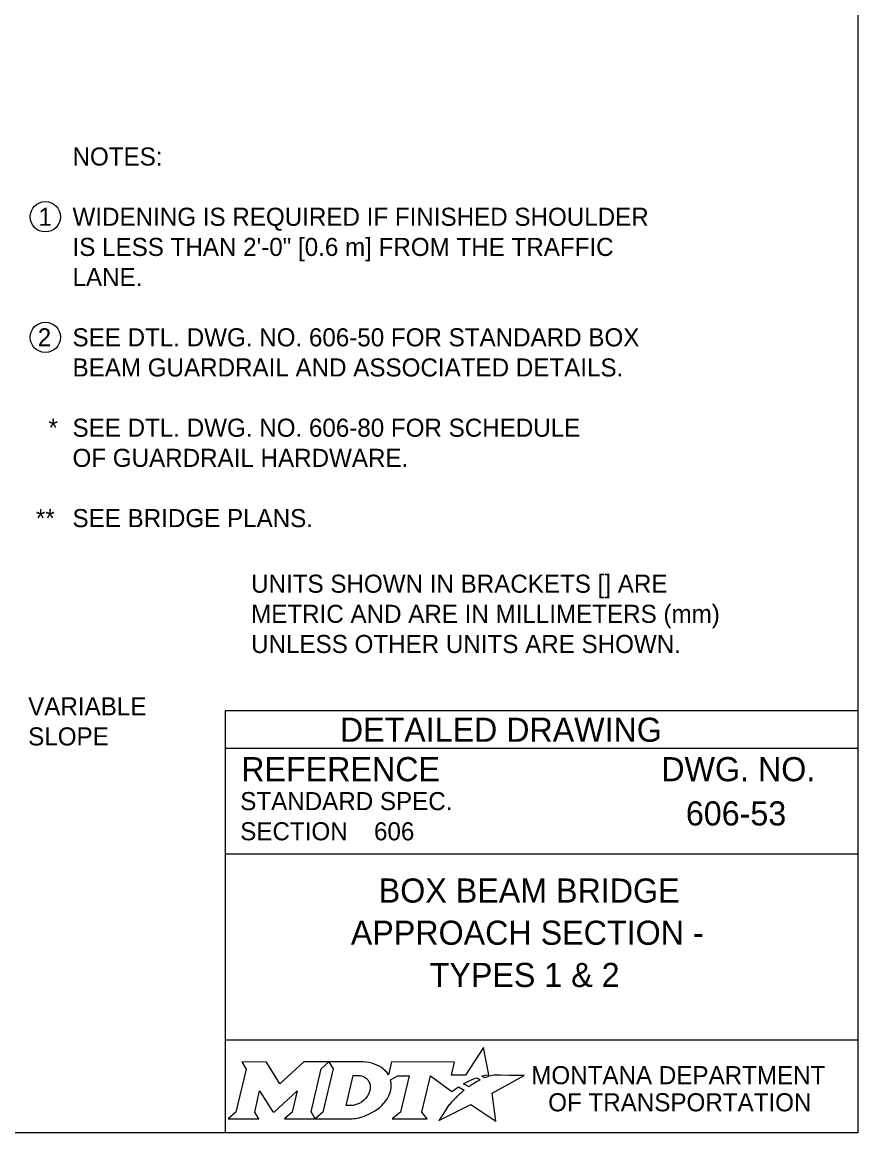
# Model space of a CAD drawing. Extents: x 49991.4 to 50021, y 49987.6 to 50011.4.
# Drawn here: x 50013.977 to 50016.75, y 49987.799 to 49991.484 of the extents above; entities that cross this region are included whole.
import ezdxf

# ---------------------------------------------------------------- set-up
doc = ezdxf.new("R2010")
doc.units = 0
for name, color, linetype in [('Default', 7, 'Continuous'), ('Level 1', 7, 'Continuous'), ('Level 2', 7, 'Continuous'), ('Level 5', 7, 'Continuous')]:
    doc.layers.add(name, color=color, linetype=linetype)

msp = doc.modelspace()

# ---------------------------------------------------------------- linework, layer by layer
at = {"layer": 'Default'}
for points in [[(50015.5126, 49987.9811), (50015.5023, 49987.9867), (50015.5139, 49987.9895), (50015.5255, 49987.9915), (50015.5081, 49988.0816), (50015.4486, 49987.9903), (50015.4013, 49987.9896), (50015.4116, 49988.0337), (50015.2024, 49988.0338), (50015.1923, 49987.9913), (50015.1865, 49987.9996)], [(50014.7056, 49988.0338), (50014.7197, 49988.0104), (50014.6862, 49987.8671), (50014.6605, 49987.8446), (50014.7621, 49987.8446), (50014.7486, 49987.8674), (50014.7648, 49987.9375), (50014.8085, 49987.8685), (50014.8138, 49987.8685), (50014.8889, 49987.938), (50014.8725, 49987.8669), (50014.8478, 49987.8449), (50014.9494, 49987.8449), (50014.9356, 49987.8682), (50014.9688, 49988.0106)], [(50014.9688, 49988.0106), (50014.9941, 49988.0338), (50014.9117, 49988.0338), (50014.8321, 49987.9608), (50014.7876, 49988.0335), (50014.7056, 49988.0338)], [(50015.1077, 49988.0338), (50014.9941, 49988.0338), (50015.0088, 49988.0109), (50014.9749, 49987.8671), (50014.9494, 49987.8449), (50015.06, 49987.8449)], [(50015.1317, 49987.9471), (50015.1305, 49987.939), (50015.1273, 49987.9297), (50015.1231, 49987.9215), (50015.1175, 49987.914), (50015.111, 49987.9071), (50015.1031, 49987.9008), (50015.0948, 49987.8961), (50015.0857, 49987.8922), (50015.0766, 49987.8899), (50015.0674, 49987.889), (50015.0515, 49987.889), (50015.0751, 49987.989), (50015.0911, 49987.989), (50015.0987, 49987.9884), (50015.1063, 49987.9865), (50015.1129, 49987.9835), (50015.119, 49987.9793), (50015.1238, 49987.9743), (50015.1275, 49987.9683), (50015.1302, 49987.9621), (50015.1318, 49987.9547), (50015.1318, 49987.9517), (50015.1317, 49987.9471)], [(50015.1991, 49987.9747), (50015.2237, 49987.9878), (50015.2606, 49987.9878), (50015.232, 49987.8673), (50015.2045, 49987.8446), (50015.3207, 49987.8446), (50015.3037, 49987.8675), (50015.3319, 49987.9877), (50015.4032, 49987.936), (50015.4243, 49987.9511), (50015.444, 49987.9402)], [(50015.3882, 49987.8843), (50015.3729, 49987.8599), (50015.3682, 49987.8524), (50015.3624, 49987.8438), (50015.3601, 49987.8395), (50015.4654, 49987.8926), (50015.5493, 49987.8375), (50015.5362, 49987.9302), (50015.6431, 49987.9886), (50015.5938, 49987.9894), (50015.5637, 49987.9898), (50015.5429, 49987.9901), (50015.5361, 49987.9886), (50015.5312, 49987.9874), (50015.5228, 49987.9851), (50015.5126, 49987.9811)], [(50015.4622, 49987.9535), (50015.4598, 49987.9518), (50015.4415, 49987.9614), (50015.4518, 49987.9671), (50015.4559, 49987.9693), (50015.4645, 49987.9733), (50015.4702, 49987.9759), (50015.4781, 49987.9789), (50015.4854, 49987.9816), (50015.4972, 49987.9742), (50015.4932, 49987.9721), (50015.4886, 49987.9696), (50015.4844, 49987.9674), (50015.4794, 49987.9645), (50015.4775, 49987.9634), (50015.4748, 49987.9618), (50015.4723, 49987.9604), (50015.47, 49987.9588), (50015.4674, 49987.957), (50015.4647, 49987.9552), (50015.4622, 49987.9535)], [(50015.1057, 49987.8522), (50015.1141, 49987.8548), (50015.1271, 49987.8602), (50015.1475, 49987.8712)], [(50015.4021, 49987.9004), (50015.4021, 49987.9004)]]:
    msp.add_lwpolyline(points, dxfattribs=at)
for centre, radius, start, end in [((50015.1308, 49987.9554), 0.0709, 339.5329, 15.8582), ((50015.0868, 49987.9727), 0.1183, 300.9103, 339.1383)]:
    msp.add_arc(centre, radius, start, end, dxfattribs=at)
for centre, major_axis, ratio, start_param, end_param in [((50015.1056, 49987.9864), (0.0834, -0.0037), 0.568097, 0.61298, 1.570796), ((50015.1612, 49987.9937), (0.0361, -0.0295), 0.469099, 1.225588, 1.570796), ((50015.4119, 49987.9106), (-0.0098, -0.0102), 0.016458, 3.141593, 6.279097), ((50015.4329, 49987.9305), (-0.0112, -0.0097), 0.021651, 3.157348, 6.283185), ((50015.3952, 49987.8923), (-0.00694, -0.00806), 0.008222, 0, 3.137361), ((50015.0603, 49987.9932), (0, 0.1484), 0.987302, 3.139398, 3.456847)]:
    msp.add_ellipse(centre, major_axis=major_axis, ratio=ratio, start_param=start_param, end_param=end_param, dxfattribs=at)
at = {"layer": 'Level 1'}
msp.add_lwpolyline([(49999.3835, 49998.9992), (50016.7501, 49998.9992), (50016.7501, 49987.7988), (49999.3835, 49987.7988)], close=True, dxfattribs=at)
at = {"layer": 'Level 2'}
for centre in [(50014.0535, 49990.8385), (50014.0535, 49990.4385)]:
    msp.add_circle(centre, 0.0503, dxfattribs=at)
at = {"layer": 'Level 5'}
for p, q in [((50016.7501, 49989.1988), (50014.6501, 49989.1988)), ((50014.6501, 49989.1988), (50014.6501, 49987.7988)), ((50016.7501, 49989.0738), (50014.6501, 49989.0738)), ((50016.3862, 49988.8587), (50016.3862, 49988.8587)), ((50015.1444, 49988.7993), (50015.1444, 49988.7993)), ((50016.7501, 49988.7238), (50014.6501, 49988.7238)), ((50015.7001, 49988.4747), (50015.7001, 49988.4747)), ((50016.7501, 49988.1057), (50014.6501, 49988.1057))]:
    msp.add_line(p, q, dxfattribs=at)

# ---------------------------------------------------------------- texts
at = {"layer": 'Default'}
for s, p in [('MONTANA DEPARTMENT', (50015.6663, 49987.96)), ('OF TRANSPORTATION', (50015.7225, 49987.87))]:
    msp.add_text(s, height=0.06, dxfattribs=at).set_placement(p)
at = {"layer": 'Level 2'}
for s, height, p in [('NOTES:', 0.06, (50014.1438, 49991.0085)), ('1', 0.06, (50014.0308, 49990.8085)), ('WIDENING IS REQUIRED IF FINISHED SHOULDER', 0.06, (50014.1438, 49990.8085)), ('IS LESS THAN 2\'-0" [0.6 m] FROM THE TRAFFIC ', 0.06, (50014.1438, 49990.7085)), ('LANE.', 0.06, (50014.1438, 49990.6085)), ('2', 0.06, (50014.0284, 49990.4085)), ('SEE DTL. DWG. NO. 606-50 FOR STANDARD BOX ', 0.06, (50014.1438, 49990.4085)), ('BEAM GUARDRAIL AND ASSOCIATED DETAILS.', 0.06, (50014.1438, 49990.3085)), ('*', 0.06, (50014.064, 49990.1085)), ('SEE DTL. DWG. NO. 606-80 FOR SCHEDULE', 0.06, (50014.1438, 49990.1085)), ('OF GUARDRAIL HARDWARE.', 0.06, (50014.1438, 49990.0085)), ('**', 0.06, (50014.0224, 49989.8085)), ('SEE BRIDGE PLANS.', 0.06, (50014.1438, 49989.8085)), ('UNITS SHOWN IN BRACKETS [] ARE ', 0.06, (50014.7365, 49989.5909)), ('METRIC AND ARE IN MILLIMETERS (mm) ', 0.06, (50014.7365, 49989.4909)), ('UNLESS OTHER UNITS ARE SHOWN.', 0.06, (50014.7365, 49989.3909)), ('VARIABLE', 0.06, (50013.9966, 49989.1841)), ('SLOPE', 0.06, (50013.9966, 49989.0841)), ('606-53', 0.08, (50016.1795, 49988.8187)), ('606', 0.06, (50015.1444, 49988.7693)), ('BOX BEAM BRIDGE', 0.08, (50015.1601, 49988.5627)), ('APPROACH SECTION -', 0.08, (50015.0674, 49988.4227)), ('TYPES 1 & 2', 0.08, (50015.3292, 49988.2827))]:
    msp.add_text(s, height=height, dxfattribs=at).set_placement(p)
at = {"layer": 'Level 5'}
for s, height, p in [('DETAILED DRAWING', 0.0799, (50015.0311, 49989.0963)), ('REFERENCE', 0.08, (50014.7037, 49988.9654)), ('DWG. NO.', 0.08, (50016.0979, 49988.9654)), ('STANDARD SPEC.', 0.06, (50014.7004, 49988.8694)), ('SECTION', 0.06, (50014.7004, 49988.7694))]:
    msp.add_text(s, height=height, dxfattribs=at).set_placement(p)

doc.saveas('drawing.dxf')
